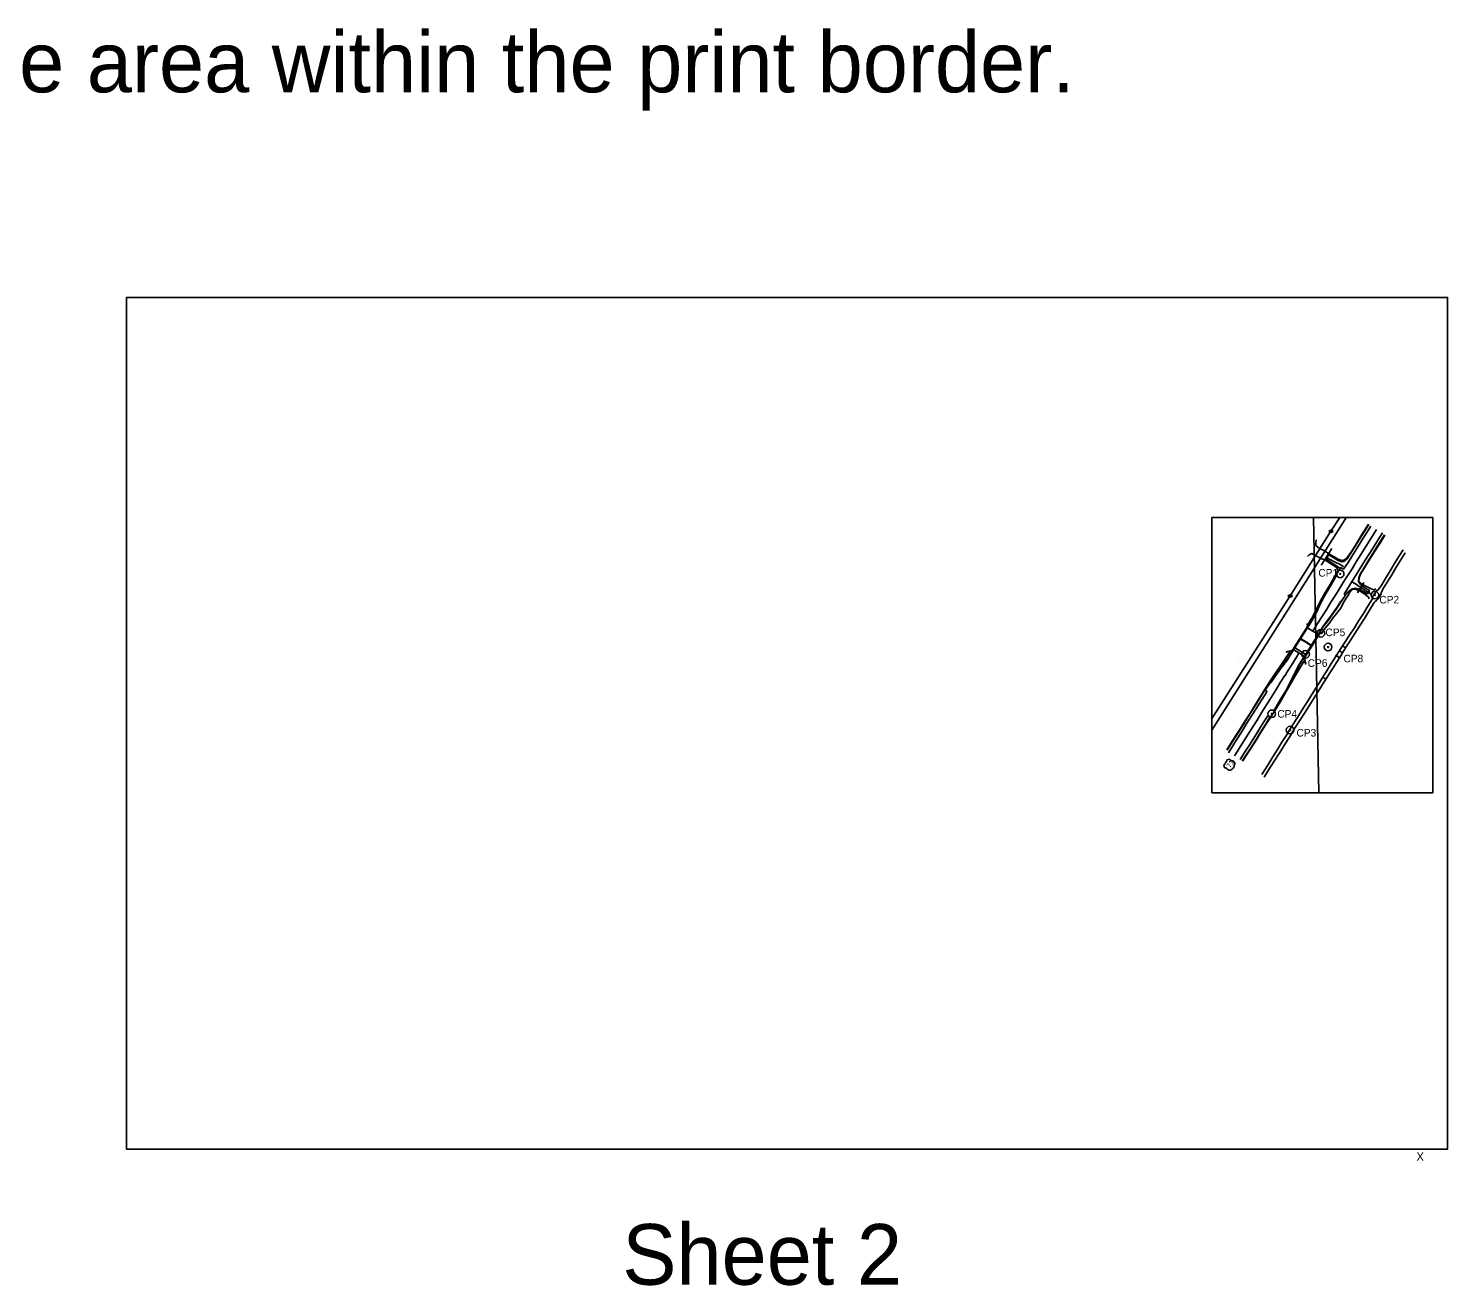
# Model space of a CAD drawing. Extents: x 10133 to 81668, y 7600 to 10582.
# Drawn here: x 13500 to 16868, y 7600 to 10582 of the extents above; entities that cross this region are included whole.
import ezdxf

# ---------------------------------------------------------------- set-up
doc = ezdxf.new("R2010")
doc.units = 0
for name, color, linetype in [('Alignment', 7, 'Continuous'), ('Bridge', 7, 'Continuous'), ('Concrete', 7, 'Continuous'), ('Default', 7, 'Continuous'), ('Roadways', 7, 'Continuous'), ('SurDrainage', 7, 'Continuous'), ('SurPointsNonDTM', 7, 'Continuous'), ('SurRoadPoints', 7, 'Continuous'), ('SurSurveyPoints', 7, 'Continuous'), ('SurTopOfWater', 7, 'Continuous'), ('SurUtilityPoleCell', 7, 'Continuous'), ('tdCoCityStreetMinor', 7, 'Continuous'), ('tdCoCorpBndry', 7, 'Continuous'), ('Terrain', 7, 'Continuous'), ('Topography', 7, 'Continuous')]:
    doc.layers.add(name, color=color, linetype=linetype)

msp = doc.modelspace()

# ---------------------------------------------------------------- linework, layer by layer
at = {"layer": 'Bridge'}
for p, q in [((16544.9, 9118.6), (16538.7, 9122.5)), ((16601.8, 9095), (16601.8, 9095)), ((16604.3, 9093.4), (16604.3, 9093.4)), ((16612, 9105.1), (16612, 9105.1)), ((16614, 9103.6), (16614, 9103.6)), ((16616.4, 9101.7), (16616.4, 9101.7)), ((16607.5, 9091.6), (16607.5, 9091.6)), ((16609.8, 9090.2), (16609.8, 9090.2)), ((16612, 9088.9), (16612, 9088.9))]:
    msp.add_line(p, q, dxfattribs=at)
for points in [[(16502.1, 9108.4), (16511.4, 9123.1), (16519.3, 9136), (16527.7, 9149.2), (16534.8, 9160.4), (16533.2, 9161.3), (16524.5, 9147.3), (16515.5, 9132.8), (16508.3, 9121.5), (16500.7, 9109.4)], [(16533.9, 9160.8), (16533.9, 9160.8), (16534.5, 9160.5), (16519, 9135.9), (16501.9, 9108.7), (16501.4, 9109), (16516.2, 9132.7)], [(16533.9, 9160.8), (16516.2, 9132.7)], [(16518.2, 9136.2), (16518.2, 9136.2)], [(16518.8, 9133.5), (16525.3, 9129.5), (16531, 9126), (16538, 9121.5), (16544.2, 9117.6)], [(16538.7, 9122.5), (16532.4, 9126.6), (16526, 9130.5), (16519.6, 9134.5)], [(16561.9, 9143.3), (16554.6, 9131.8), (16545, 9116.5), (16537.2, 9104.2), (16529.4, 9091.7), (16527.9, 9092.6), (16535, 9104), (16544.1, 9118.4), (16552.3, 9131.5), (16560.5, 9144.2)], [(16560.7, 9144.1), (16544.3, 9118.4), (16528.2, 9092.6), (16528.8, 9092.2), (16542.5, 9114.2)], [(16533.8, 9126.4), (16533.9, 9126.4)], [(16542.5, 9114.2), (16561.2, 9143.7)], [(16538, 9121.5), (16538.7, 9122.5)], [(16544.2, 9117.6), (16544.9, 9118.6)], [(16545.9, 9118.7), (16545.9, 9118.7)], [(16618.3, 9117.3), (16612.9, 9109.2), (16604.7, 9095.9), (16596.2, 9082.5), (16588.4, 9069.9), (16580.8, 9058), (16571.7, 9043.8)], [(16579.1, 9039), (16588, 9053.3), (16595.8, 9065.2), (16603.8, 9078), (16612.3, 9091.4), (16620.5, 9104.6), (16625.5, 9112.4)], [(16610.6, 9090), (16603.9, 9094.1)], [(16617.1, 9101), (16611.4, 9105.6)]]:
    msp.add_lwpolyline(points, dxfattribs=at)
for points in [[(16519.3, 9133.2), (16520, 9134.2), (16519, 9134.9), (16518.3, 9133.9)], [(16525.3, 9129.5), (16526, 9130.5), (16525, 9131.2), (16524.3, 9130.1)], [(16531.8, 9125.4), (16532.5, 9126.4), (16531.5, 9127.1), (16530.8, 9126.1)], [(16538, 9121.5), (16538.7, 9122.5), (16537.6, 9123.2), (16537, 9122.2)], [(16544.2, 9117.6), (16544.9, 9118.6), (16543.9, 9119.3), (16543.2, 9118.3)], [(16601.8, 9095), (16612, 9088.9), (16612.1, 9089.2), (16602, 9095.3)], [(16611.4, 9105.6), (16617.1, 9101), (16617.3, 9101.3), (16611.6, 9105.8)]]:
    msp.add_lwpolyline(points, close=True, dxfattribs=at)
at = {"layer": 'Concrete'}
for p, q in [((16336.5, 8835.1), (16338.3, 8828.2)), ((16350.3, 8849), (16343.5, 8847.2)), ((16356.6, 8825.8), (16357.1, 8826.7)), ((16361.1, 8833.6), (16361.6, 8834.5))]:
    msp.add_line(p, q, dxfattribs=at)
for centre, radius, start, end in [((16335.2, 8839.9), 5, 285.5729, 14.4272), ((16339, 8821.3), 7, 34.9895, 95.6629), ((16338.7, 8845.9), 5, 285.5729, 14.4272), ((16350.5, 8829.3), 7, 214.9897, 330.0001), ((16356.7, 8851.9), 7, 204.3372, 265.01), ((16355.5, 8838), 7, 330.0001, 85.0104), ((16361.4, 8824.2), 5, 96.8699, 150.0002), ((16365.4, 8831.1), 5, 150.0002, 203.13)]:
    msp.add_arc(centre, radius, start, end, dxfattribs=at)
at = {"layer": 'Default'}
msp.add_lwpolyline([(13732.5, 9944), (16867.5, 9944), (16867.5, 7924), (13732.5, 7924)], close=True, dxfattribs=at)
at = {"layer": 'Roadways'}
for p, q in [((16590.8, 9389.2), (16611.5, 9422)), ((16494.3, 9236.1), (16590.8, 9389.2)), ((16307.6, 8943.3), (16494.3, 9236.1))]:
    msp.add_line(p, q, dxfattribs=at)
at = {"layer": 'SurDrainage'}
for points in [[(16685.4, 9401.8), (16674.2, 9384), (16663.2, 9366.4), (16651.9, 9348.5), (16639.9, 9329.6), (16629.6, 9313.2), (16620.3, 9299.4), (16613.6, 9303.1), (16603.2, 9285.7), (16594.5, 9270.2), (16585.1, 9253.8), (16575.8, 9237.8), (16566.9, 9221.5), (16558.6, 9204.5), (16553.1, 9193.3), (16547.1, 9182.6), (16544.6, 9178), (16545, 9177.7)], [(16679.7, 9405.8), (16663.5, 9380.2), (16649, 9356.7), (16641, 9343.8), (16628, 9324.9), (16620, 9320.3), (16615.8, 9320.6), (16609.2, 9322.4), (16598.6, 9328.6), (16587.3, 9335.3), (16575.1, 9342.6), (16563.6, 9348.8), (16555.2, 9355.7), (16554.5, 9362.9), (16555.3, 9369.4)], [(16680.5, 9405.2), (16664.3, 9379.7), (16649.7, 9356.3), (16641.7, 9343.5), (16628.9, 9324), (16621.4, 9317.4), (16615.7, 9316.5), (16607.9, 9320), (16597.6, 9326.6), (16585.2, 9333.2), (16579.4, 9323.9), (16591.1, 9315.6), (16602.3, 9308.3), (16610.1, 9302.7), (16610.6, 9298.7)], [(16547.4, 9152.2), (16558.7, 9170.2), (16570.3, 9188.4), (16580.6, 9204.7), (16590.8, 9221), (16601.5, 9238.1), (16610.4, 9252.1), (16619.9, 9267.6), (16630.2, 9283.9), (16640.7, 9300.6), (16650.8, 9317), (16661.5, 9334), (16675.2, 9355.7), (16687.3, 9374.9), (16699.1, 9393.8)], [(16713, 9385.8), (16702, 9368), (16690.8, 9350.3), (16679.2, 9331.8), (16668.2, 9314.4), (16656.9, 9296), (16645.3, 9277.7), (16634.8, 9260.8), (16622.3, 9240.3), (16625.5, 9237.6), (16615.3, 9222.8), (16603.5, 9205.6), (16592.9, 9190.2), (16581.8, 9174.9), (16571, 9160.7)], [(16717.9, 9381), (16705.3, 9361.2), (16692.5, 9340.5), (16680.7, 9321.4), (16670.2, 9304.5), (16660, 9287.8), (16656.6, 9279.2), (16656.3, 9270.5), (16661.2, 9263.2), (16669.9, 9256.1), (16682, 9248.9), (16677.3, 9240.8), (16669.1, 9245.8), (16658.6, 9251.8), (16649.3, 9254.3), (16640.9, 9252.8), (16631.8, 9245.4), (16625.9, 9239.3)], [(16718.6, 9380.4), (16706.5, 9360.5), (16693.3, 9340.1), (16681.4, 9320.9), (16671.1, 9304), (16660.7, 9287.5), (16657.7, 9279.1), (16656.9, 9270.9), (16662.9, 9264.5), (16671.9, 9259.6), (16684.4, 9253.3), (16692.6, 9250.4), (16697, 9252.7)], [(16535, 9329.2), (16539.1, 9333.4), (16545.1, 9336.9), (16556, 9330.8), (16567.1, 9324.4), (16577.6, 9320.5), (16590.2, 9312), (16600.5, 9305.4), (16604.3, 9303), (16606.2, 9295.8), (16599.1, 9281.2), (16589.2, 9263.4), (16577.1, 9243.8), (16565.5, 9222.6), (16555, 9201.3), (16545.3, 9183.1), (16536.8, 9169.7)], [(16762, 9345.7), (16752, 9329.4), (16741.6, 9312.5), (16731, 9295.3), (16720.1, 9277.4), (16709.6, 9260.3), (16702.6, 9250.5), (16699.4, 9249), (16689.6, 9233.7), (16689.1, 9229.1), (16678.5, 9211.4), (16668, 9194.3), (16657.1, 9177.4), (16646.4, 9160.5), (16635.1, 9142.9), (16623.2, 9124.6), (16618.3, 9117.2), (16625.6, 9112.7)], [(16625.6, 9112.7), (16636.1, 9129.2), (16647.7, 9146.9), (16658.5, 9164), (16670.1, 9182.2), (16682.5, 9202.3), (16693.6, 9220), (16695.8, 9222.9), (16698.5, 9225.2), (16700.4, 9226.7), (16702.4, 9229.3), (16708.7, 9239), (16709.9, 9241.7), (16710, 9243.1), (16712.1, 9247.9), (16713.8, 9251.8), (16724.3, 9268.9), (16734.9, 9286.1), (16744.7, 9302.5), (16755, 9319.2), (16766.6, 9337.8)], [(16581.9, 9326.4), (16599.3, 9316.5), (16614.2, 9309.4), (16620.6, 9305.3)], [(16688.1, 9239.2), (16673.7, 9248.3), (16660.2, 9257), (16648.6, 9264.4), (16641.6, 9268.6)], [(16681.7, 9229.3), (16679.6, 9233.1), (16670.8, 9240.1), (16660.4, 9247.2), (16649.1, 9251.8), (16642.2, 9250.9), (16635.1, 9243), (16630.4, 9236), (16621.5, 9222.2), (16614.3, 9207.3), (16604.7, 9195.2), (16594.7, 9182.4), (16586.5, 9170.9), (16576.9, 9159.2), (16570, 9148.8)], [(16544.9, 9177.5), (16544.4, 9176.7), (16537.2, 9165.4), (16536.3, 9162.4), (16534.9, 9160.3)], [(16560.2, 9144.3), (16558.3, 9145.9), (16547.4, 9152.2), (16537.2, 9158.9), (16534.9, 9160.3)], [(16570.9, 9160.6), (16570.6, 9160.1), (16564, 9148.9), (16563.8, 9148.7), (16561.6, 9146.5), (16560.2, 9144.3)], [(16343.4, 8870.7), (16356.4, 8891.5), (16371.2, 8914.6), (16385.6, 8937.1), (16399.5, 8959), (16412.6, 8979.7), (16426.1, 9001.7), (16433.3, 9013.1), (16444.3, 9030.4), (16456.7, 9049.3), (16471.3, 9070), (16483.5, 9089.4), (16493.2, 9102.3)], [(16362, 8856.7), (16372.7, 8873.9), (16383.5, 8890.8), (16394.3, 8908.2), (16405.4, 8925.7), (16415.3, 8941.3), (16427, 8960.4), (16438.1, 8978), (16449, 8995.4), (16460.6, 9013.8), (16471.4, 9031.1), (16481.6, 9047.2), (16482, 9047.4), (16487.2, 9055.9), (16500.4, 9076.8), (16511.4, 9094.7), (16514.9, 9100.7)], [(16491.4, 9092.5), (16491.7, 9092.7), (16498.5, 9103.8)], [(16498.5, 9103.8), (16501, 9106.3), (16502.5, 9108.6)], [(16527.9, 9093), (16525.8, 9094), (16514.9, 9100.7), (16504.7, 9106.9), (16502.5, 9108.6)], [(16347.3, 8863.6), (16357.8, 8880.4), (16359, 8882.2), (16369.5, 8899), (16380.6, 8916.9), (16391.5, 8934.1), (16402.2, 8951.2), (16413.7, 8969.5), (16424.4, 8986.5), (16435.9, 9004.8), (16438.9, 9009.8), (16434.8, 9012.4), (16446.4, 9029.6), (16456.5, 9044.4), (16465.8, 9057.5), (16476.3, 9072), (16486.1, 9085.2), (16491.2, 9092.2)], [(16375.3, 8847.8), (16385.6, 8864.5), (16396.3, 8881.5), (16407.4, 8898.7), (16418.6, 8916.6), (16430.2, 8934.6), (16440.6, 8951.6), (16446.9, 8948.4), (16457.2, 8963.7), (16468.1, 8982.5), (16477.7, 8999.1), (16487.2, 9015.2), (16496.1, 9031.8), (16504.1, 9048.7), (16512.4, 9065.5), (16517.9, 9075.7)], [(16381.2, 8844.3), (16396, 8866.8), (16410.8, 8889.8), (16423.9, 8910.9), (16436.5, 8930.9), (16447.2, 8947.4), (16458.6, 8964.9), (16470.7, 8985.2), (16481.6, 9003.9), (16492, 9022.6), (16502.2, 9039.1), (16512.6, 9058.5), (16522.1, 9073.9), (16527.2, 9081.5)], [(16518.1, 9075.9), (16518.5, 9076.3), (16525.4, 9087.6)], [(16571.8, 9043.5), (16561.9, 9027.9), (16549.4, 9008.4), (16536.6, 8987.6), (16522.7, 8965.8), (16511.1, 8947.2), (16497.8, 8926.7), (16484.9, 8905.6), (16474.2, 8888.7), (16463.7, 8871.9), (16452.8, 8854.4), (16440.7, 8834.8), (16426.4, 8812.3)], [(16432.2, 8805.7), (16443.3, 8824), (16456.3, 8844.3), (16469.3, 8864.5), (16480.8, 8882.8), (16492, 8900.6), (16506.2, 8923.6), (16518, 8942.4), (16529.5, 8960.3), (16542.9, 8981.7), (16554.6, 9000.9), (16568.1, 9022), (16578.8, 9038.4), (16571.8, 9043.5)], [(16344.3, 8870.1), (16357.2, 8891), (16372.1, 8913.9), (16386.2, 8936.9), (16400.1, 8958.6), (16413.3, 8979.3), (16426.9, 9001), (16433.9, 9012.6)], [(16380.2, 8844.6), (16395.2, 8867.1), (16410.1, 8890.2), (16423.1, 8911.4), (16435.7, 8931.3), (16445.5, 8948)]]:
    msp.add_lwpolyline(points, dxfattribs=at)
at = {"layer": 'SurPointsNonDTM'}
for p, q in [((16308, 8917.8), (16627.8, 9423.1)), ((16369.3, 9084.4), (16369.3, 9084.4)), ((16371.7, 9089.3), (16371.7, 9089.3))]:
    msp.add_line(p, q, dxfattribs=at)
at = {"layer": 'SurRoadPoints'}
for centre, radius in [((16612.6, 9288.2), 9), ((16612.6, 9288.2), 1.12), ((16695, 9238.1), 9), ((16695, 9238.1), 1.12), ((16566.9, 9147.5), 9), ((16566.9, 9147.5), 1.12), ((16530.5, 9097.7), 9), ((16530.5, 9097.7), 1.12), ((16583.9, 9114.6), 9), ((16583.9, 9114.6), 1.12), ((16450.3, 8956.3), 9), ((16450.3, 8956.3), 1.12), ((16493.8, 8917.8), 9), ((16493.8, 8917.8), 1.12)]:
    msp.add_circle(centre, radius, dxfattribs=at)
at = {"layer": 'SurSurveyPoints'}
for p, q in [((16585.3, 9390.3), (16596.3, 9390.3)), ((16585.3, 9388.1), (16596.3, 9388.1)), ((16488.8, 9237.2), (16499.8, 9237.2)), ((16488.8, 9235), (16499.8, 9235))]:
    msp.add_line(p, q, dxfattribs=at)
for centre in [(16590.8, 9389.2), (16494.3, 9236.1)]:
    msp.add_circle(centre, 2.75, dxfattribs=at)
at = {"layer": 'SurTopOfWater'}
for points in [[(16536.3, 9162.4), (16543, 9173.3), (16549.6, 9184.2), (16556.9, 9197.9), (16562.3, 9209.2), (16567.7, 9220.2), (16573.4, 9231.5), (16579.7, 9242.4), (16586, 9253.1), (16592.2, 9263.9), (16598.4, 9274.6), (16605.8, 9287.9)], [(16614.1, 9223.4), (16605.9, 9211.1), (16598.9, 9200.9), (16591.8, 9190.7), (16584.6, 9180.6), (16577.1, 9170.5), (16571.7, 9162.6), (16561.6, 9146.5)], [(16447.7, 9029.5), (16456, 9041.6), (16466.9, 9057.1), (16474.2, 9067), (16481.8, 9076.9), (16487.4, 9084.7), (16494.2, 9095.1), (16501, 9106.3)], [(16526.4, 9090.8), (16519.6, 9079.8), (16513.2, 9069.1), (16505.9, 9055.3), (16500.5, 9044), (16495.1, 9032.7), (16489.4, 9021.7), (16483.3, 9010.9), (16476.9, 9000.1), (16470.6, 8989.5), (16464.2, 8978.6), (16456.4, 8965.5)]]:
    msp.add_lwpolyline(points, dxfattribs=at)
at = {"layer": 'SurUtilityPoleCell'}
for points in [[(16568, 9309), (16568.1, 9309.5), (16592.8, 9348.6)], [(16653.4, 9243.2), (16668.6, 9267.8)]]:
    msp.add_lwpolyline(points, dxfattribs=at)
at = {"layer": 'tdCoCorpBndry'}
msp.add_lwpolyline([(16308.1, 9421.7), (16832.7, 9421.7), (16832.7, 8769.2), (16308.1, 8769.2)], close=True, dxfattribs=at)
at = {"layer": 'Terrain'}
msp.add_lwpolyline([(16562, 8768.6), (16549, 9422.2)], dxfattribs=at)
at = {"layer": 'Topography'}
for points in [[(16535, 9160.8), (16533.2, 9161.5), (16534.8, 9164.3), (16534.2, 9168), (16535.6, 9168.3)], [(16535, 9160.8), (16536.2, 9163.2), (16536.9, 9165.1), (16536.4, 9165.5), (16533.7, 9161.4)], [(16534.3, 9168.1), (16534, 9169.3), (16534.8, 9169.5), (16535, 9168.3)], [(16560.7, 9144.1), (16560.9, 9144.5), (16562.4, 9146.9), (16563.7, 9148.4), (16564.5, 9147.9), (16561.8, 9143.8), (16561.2, 9143.7)], [(16564.3, 9147.6), (16567.3, 9148.3), (16567.6, 9147.8), (16567.7, 9147.8), (16569.2, 9148.1), (16569.3, 9147.3), (16567.8, 9147), (16567.7, 9146.8), (16563.8, 9146.1), (16562.2, 9143.4)], [(16494.5, 9104.9), (16484.9, 9102.9), (16484.8, 9103.6), (16494.4, 9105.6)], [(16498.3, 9105.3), (16494.8, 9104.5), (16494.6, 9105.6), (16498.5, 9106.7), (16500.3, 9109.2), (16501.7, 9108.3)], [(16501.7, 9108.3), (16500.3, 9105.9), (16498.7, 9104.4), (16498.2, 9104.8)], [(16498.2, 9104.8), (16498.3, 9105.3)], [(16530.5, 9093.2), (16529.3, 9097.7), (16506.3, 9112.2), (16500.7, 9110.9)], [(16527.9, 9092.4), (16529.5, 9091.5), (16528, 9088.8), (16527.9, 9088.8), (16528.7, 9084.9), (16527.3, 9084.5), (16526.7, 9087.8)], [(16526.2, 9087.6), (16528.9, 9091.6), (16527.9, 9092.2), (16526.3, 9089.7), (16525.7, 9087.9)], [(16528.8, 9084.7), (16531, 9074.8), (16530.3, 9074.7), (16527.9, 9084.4)]]:
    msp.add_lwpolyline(points, dxfattribs=at)

# ---------------------------------------------------------------- texts
at = {"layer": 'Alignment'}
msp.add_text('X', height=20, dxfattribs=at).set_placement((16793.6, 7896))
at = {"layer": 'Concrete'}
msp.add_text('71', height=12, rotation=60, dxfattribs=at).set_placement((16352.5, 8826.7))
at = {"layer": 'tdCoCityStreetMinor'}
for s, height, p in [('The boxes below encompass the usable area within the print border.', 144, (10149.1, 10430.6)), ('CP1', 18, (16560.8, 9281.8)), ('CP2', 18, (16705.6, 9218.1)), ('CP5', 18, (16577.8, 9140.6)), ('CP8', 18, (16620.4, 9078.4)), ('CP6', 18, (16535.5, 9067.7)), ('CP4', 18, (16463.5, 8947.3)), ('CP3', 18, (16509, 8902.4)), ('Sheet 2', 144, (14909.3, 7602))]:
    msp.add_text(s, height=height, dxfattribs=at).set_placement(p)

doc.saveas('drawing.dxf')
